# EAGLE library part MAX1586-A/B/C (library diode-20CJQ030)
Maxim's MAX1586/MAX1587 High-Efficiency, Low-IQ PMICs with Dynamic Core for PDAs and Smart Phones General Description: The MAX1586/MAX1587 power-management ICs are optimized for devices using Intel X-Scale microprocessors, including Smart Phones, PDAs, internet appliances, and other portable devices requiring substantial computing and multimedia capability at low power. The ICs integrate seven high-performance, low-operatingcurrent power supplies along with supervisory and management functions. Included are three step-down DC-DC outputs, three linear regulators, and a seventh always-on output. DC-DC converters power I/O, DRAM, and the CPU core. The I/O supply can be preset to 3.3V or adjusted to other values. The DRAM supply on the A and C devices is preset for 1.8V or 2.5V, while the MAX1586B DRAM supply is preset for 3.3V or 2.5V. The DRAM supply on all parts can also be adjusted with external resistors. The CPU core supply is serial programmed for dynamic voltage management and, on C devices, can supply up to 0.9A. Linear-regulated outputs are provided for SRAM, PLL, and USIM supplies. To minimize quiescent current, critical power supplies have bypass 'sleep' LDOs that can be activated when output current is very low. Other functions include separate on/off control for all DC-DC converters, low-battery and dead-battery detection, a reset and power-OK output, a backup-battery input, and a two-wire serial interface. All DC-DC outputs use fast, 1MHz PWM switching and small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
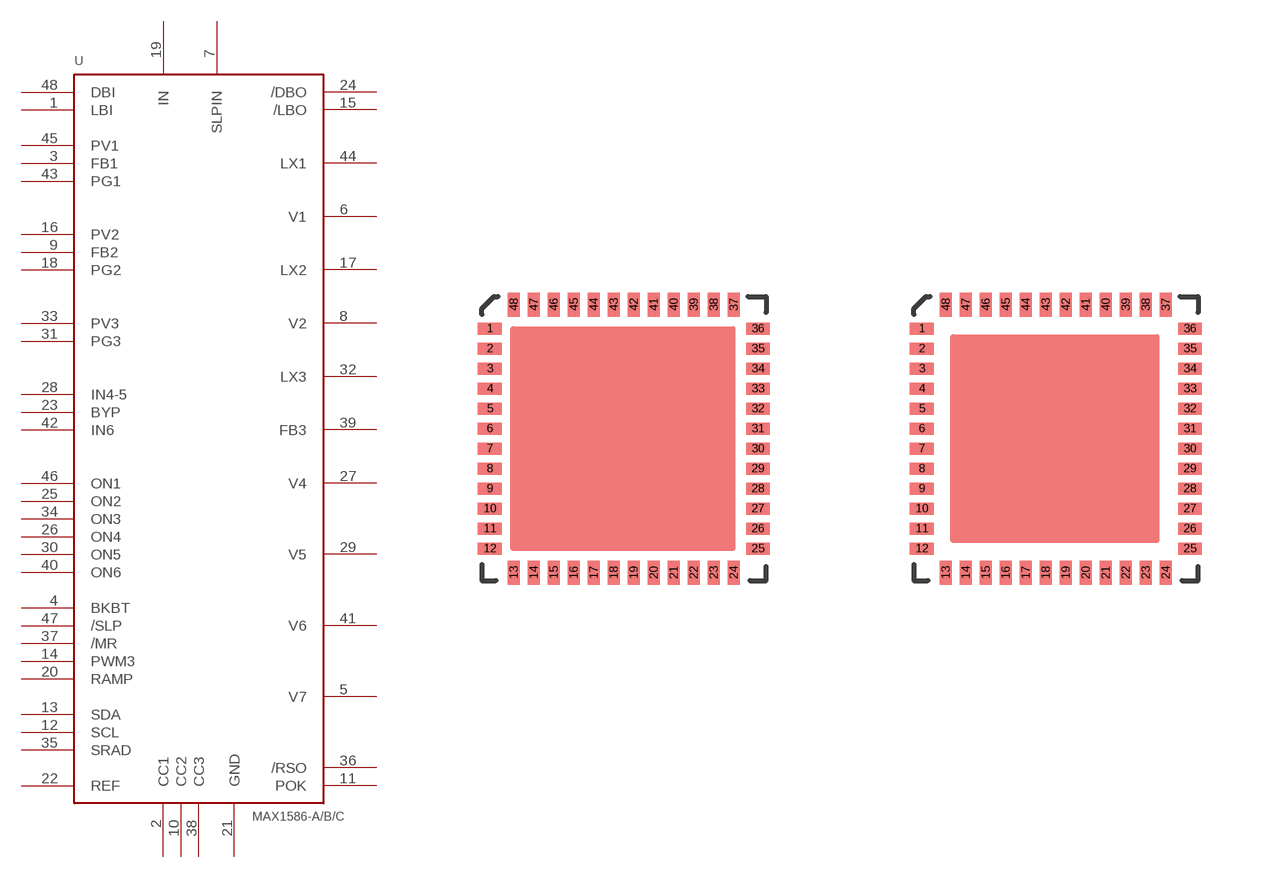
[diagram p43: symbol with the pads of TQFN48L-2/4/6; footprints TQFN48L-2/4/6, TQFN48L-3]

Designator prefix U

## MAX1586-A/B/CT4877-2/4/6  [TQFN48L-2/4/6]
1  LBI  in
2  CC1  sup
3  FB1  sup
4  BKBT  sup
5  V7  sup
6  V1  sup
7  SLPIN  pwr
8  V2  sup
9  FB2  sup
10  CC2  sup
11  POK  out
12  SCL  in
13  SDA
14  PWM3  sup
15  /LBO  out
16  PV2  sup
17  LX2  out
18  PG2  sup
19  IN  pwr
20  RAMP  sup
21  GND  pwr
22  REF  sup
23  BYP  sup
24  /DBO  out
25  ON2  in
26  ON4  in
27  V4  sup
28  IN4-5  sup
29  V5  sup
30  ON5  in
31  PG3  sup
32  LX3  out
33  PV3  sup
34  ON3  in
35  SRAD  in
36  /RSO  out
37  /MR  in
38  CC3  sup
39  FB3  in
40  ON6  in
41  V6  sup
42  IN6  sup
43  PG1  sup
44  LX1  out
45  PV1  sup
46  ON1  in
47  /SLP  in
48  DBI  in

## MAX1586-A/B/CT4877-3  [TQFN48L-3]
Pads as for TQFN48L-2/4/6

## MAX1586-A/B/CT4877-5  [TQFN48L-5]
Pads as for TQFN48L-2/4/6

## Footprint TQFN48L-2/4/6 (pad centres in mm)
smd 0.6 x 0.3: 1 -3.32,2.75; 2 -3.32,2.25; 3 -3.32,1.75; 4 -3.32,1.25; 5 -3.32,0.75; 6 -3.32,0.25; 7 -3.32,-0.25; 8 -3.32,-0.75; 9 -3.32,-1.25; 10 -3.32,-1.75; 11 -3.32,-2.25; 12 -3.32,-2.75; 25 3.38,-2.75; 26 3.38,-2.25; 27 3.38,-1.75; 28 3.38,-1.25; 29 3.38,-0.75; 30 3.38,-0.25; 31 3.38,0.25; 32 3.38,0.75; 33 3.38,1.25; 34 3.38,1.75; 35 3.38,2.25; 36 3.38,2.75
smd 0.3 x 0.6: 13 -2.72,-3.35; 14 -2.22,-3.35; 15 -1.72,-3.35; 16 -1.22,-3.35; 17 -0.72,-3.35; 18 -0.22,-3.35; 19 0.28,-3.35; 20 0.78,-3.35; 21 1.28,-3.35; 22 1.78,-3.35; 23 2.28,-3.35; 24 2.78,-3.35; 37 2.78,3.35; 38 2.28,3.35; 39 1.78,3.35; 40 1.28,3.35; 41 0.78,3.35; 42 0.28,3.35; 43 -0.22,3.35; 44 -0.72,3.35; 45 -1.22,3.35; 46 -1.72,3.35; 47 -2.22,3.35; 48 -2.72,3.35

## Footprint TQFN48L-3 (pad centres in mm)
smd 0.6 x 0.3: 1 -3.32,2.75; 2 -3.32,2.25; 3 -3.32,1.75; 4 -3.32,1.25; 5 -3.32,0.75; 6 -3.32,0.25; 7 -3.32,-0.25; 8 -3.32,-0.75; 9 -3.32,-1.25; 10 -3.32,-1.75; 11 -3.32,-2.25; 12 -3.32,-2.75; 25 3.38,-2.75; 26 3.38,-2.25; 27 3.38,-1.75; 28 3.38,-1.25; 29 3.38,-0.75; 30 3.38,-0.25; 31 3.38,0.25; 32 3.38,0.75; 33 3.38,1.25; 34 3.38,1.75; 35 3.38,2.25; 36 3.38,2.75
smd 0.3 x 0.6: 13 -2.72,-3.35; 14 -2.22,-3.35; 15 -1.72,-3.35; 16 -1.22,-3.35; 17 -0.72,-3.35; 18 -0.22,-3.35; 19 0.28,-3.35; 20 0.78,-3.35; 21 1.28,-3.35; 22 1.78,-3.35; 23 2.28,-3.35; 24 2.78,-3.35; 37 2.78,3.35; 38 2.28,3.35; 39 1.78,3.35; 40 1.28,3.35; 41 0.78,3.35; 42 0.28,3.35; 43 -0.22,3.35; 44 -0.72,3.35; 45 -1.22,3.35; 46 -1.72,3.35; 47 -2.22,3.35; 48 -2.72,3.35

## Footprint TQFN48L-5 (pad centres in mm)
smd 0.6 x 0.3: 1 -3.32,2.75; 2 -3.32,2.25; 3 -3.32,1.75; 4 -3.32,1.25; 5 -3.32,0.75; 6 -3.32,0.25; 7 -3.32,-0.25; 8 -3.32,-0.75; 9 -3.32,-1.25; 10 -3.32,-1.75; 11 -3.32,-2.25; 12 -3.32,-2.75; 25 3.38,-2.75; 26 3.38,-2.25; 27 3.38,-1.75; 28 3.38,-1.25; 29 3.38,-0.75; 30 3.38,-0.25; 31 3.38,0.25; 32 3.38,0.75; 33 3.38,1.25; 34 3.38,1.75; 35 3.38,2.25; 36 3.38,2.75
smd 0.3 x 0.6: 13 -2.72,-3.35; 14 -2.22,-3.35; 15 -1.72,-3.35; 16 -1.22,-3.35; 17 -0.72,-3.35; 18 -0.22,-3.35; 19 0.28,-3.35; 20 0.78,-3.35; 21 1.28,-3.35; 22 1.78,-3.35; 23 2.28,-3.35; 24 2.78,-3.35; 37 2.78,3.35; 38 2.28,3.35; 39 1.78,3.35; 40 1.28,3.35; 41 0.78,3.35; 42 0.28,3.35; 43 -0.22,3.35; 44 -0.72,3.35; 45 -1.22,3.35; 46 -1.72,3.35; 47 -2.22,3.35; 48 -2.72,3.35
